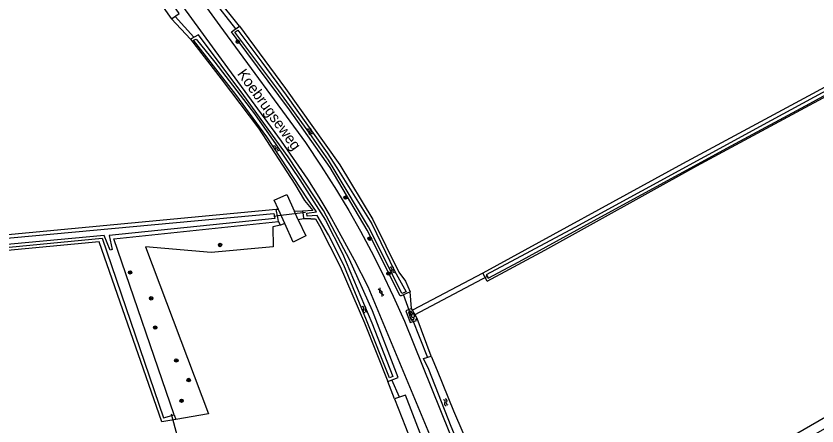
# Model space of a CAD drawing. Extents: x 135999 to 138000, y 396000 to 398501.
# Drawn here: x 136593.9 to 136779.9, y 396708.2 to 396803.6 of the extents above; entities that cross this region are included whole.
import ezdxf

# ---------------------------------------------------------------- set-up
doc = ezdxf.new("R2010")
doc.units = 0
for name, color, linetype in [('gg-anno-openbare ruimte label', 7, 'Continuous'), ('gg-knt-bronhoudergrens', 7, 'Continuous'), ('gg-knt-verharding', 7, 'Continuous'), ('gg-kntw-bovenkant insteek waterloop', 7, 'Continuous'), ('gg-kntw-waterlijn', 7, 'Continuous'), ('gg-kwrk-duiker nz buis', 7, 'Continuous'), ('gt-grn-groengrens', 7, 'Continuous'), ('gt-symb-boom', 7, 'Continuous'), ('gt-symb-gesloten verharding', 7, 'Continuous'), ('gt-symb-watersymbool', 7, 'Continuous'), ('gx-grn-maaiveld', 7, 'Continuous')]:
    doc.layers.add(name, color=color, linetype=linetype)

# ---------------------------------------------------------------- blocks, each defined once
blk = doc.blocks.new('gt0-BOOM')
at = {"layer": 'gt-symb-boom'}
for radius in [0.4, 0.2]:
    blk.add_circle((0, 0), radius, dxfattribs=at)
blk = doc.blocks.new('gt0-GESVH1')
at = {"layer": 'gt-symb-gesloten verharding'}
for p, q in [((-0.99, -0.26), (0.01, 0.24)), ((0.01, -0.26), (-0.99, 0.24)), ((0.01, 0.24), (1.01, -0.26)), ((1.01, 0.24), (0.01, -0.26))]:
    blk.add_line(p, q, dxfattribs=at)
blk = doc.blocks.new('gt0-WA')
at = {"layer": 'gt-symb-watersymbool'}
for centre, start, end in [((-0.32, 0.02), 28.0725, 151.9275), ((0.43, 0.42), 208.0725, 331.9275), ((-0.32, -0.43), 28.0725, 151.9275), ((0.43, -0.03), 208.0725, 331.9275)]:
    blk.add_arc(centre, 0.425, start, end, dxfattribs=at)

msp = doc.modelspace()

# ---------------------------------------------------------------- linework, layer by layer
at = {"layer": 'gg-knt-bronhoudergrens'}
msp.add_line((136690.33, 396724.47), (136687.07, 396733.23), dxfattribs=at)
at = {"layer": 'gg-knt-verharding'}
for points in [[(136588.1, 396874.93), (136623.71, 396825.47), (136641.24, 396801.27), (136661.13, 396774.17), (136664.79, 396768.65), (136668.32, 396763.05), (136671.15, 396758.31), (136673.86, 396753.51), (136676.36, 396748.86), (136678.74, 396744.15), (136681.48, 396738.4), (136684.08, 396732.57), (136704.84, 396681.05)], [(136584.43, 396872.45), (136602.85, 396847.13), (136623.56, 396818.2), (136641.5, 396793.5), (136655.45, 396774.43), (136661.58, 396765.61), (136664.22, 396761.4), (136666.77, 396757.13), (136668.42, 396754.23), (136672.42, 396746.85), (136675.57, 396740.66), (136690.68, 396704.38), (136701.06, 396678.66)]]:
    msp.add_lwpolyline(points, dxfattribs=at)
at = {"layer": 'gg-kntw-bovenkant insteek waterloop'}
for p, q in [((136645.78, 396801.21), (136647.97, 396798.22)), ((136654.68, 396756.7), (136654.31, 396758.54)), ((136660.45, 396758.16), (136660.57, 396757.31)), ((136654.87, 396755.74), (136654.68, 396756.7)), ((136660.57, 396757.31), (136660.69, 396756.44)), ((136662.38, 396756.42), (136663.42, 396756.43)), ((136703.31, 396741.89), (136702.32, 396743.73)), ((136703.12, 396743.36), (136703.54, 396742.62)), ((136685.99, 396735.18), (136685.78, 396735.55)), ((136687.07, 396733.23), (136685.99, 396735.18)), ((136690.33, 396724.47), (136691.7, 396721.1))]:
    msp.add_line(p, q, dxfattribs=at)
for points in [[(136630.03, 396802.89), (136631.77, 396804.16), (136609.31, 396836.49), (136592.68, 396859.89), (136581.76, 396874.66), (136580.74, 396875.78), (136580, 396876.45), (136579.14, 396877.1), (136578.27, 396877.61), (136577.36, 396878.03), (136576.41, 396878.36), (136575.74, 396878.52), (136574.76, 396878.69), (136572.96, 396878.85), (136569.96, 396878.88), (136531.18, 396875.03), (136507.77, 396872.19)], [(136508.57, 396870.21), (136524.15, 396871.93), (136546.01, 396874.18), (136561.49, 396875.6), (136569.04, 396876.21), (136573.12, 396876.33), (136575.86, 396875.99), (136577.65, 396875.22), (136579.07, 396874.22), (136581.26, 396871.43), (136598.94, 396846.62), (136614.6, 396825.01), (136629.68, 396803.27), (136630.03, 396802.89)], [(136872.6, 396836.66), (136849.59, 396824.15), (136810.91, 396802.73), (136748.71, 396769.2), (136702.32, 396743.73)], [(136703.31, 396741.89), (136716.7, 396749.13), (136752, 396768.72), (136805.5, 396797.58), (136858.35, 396826.35), (136874.16, 396834.84)], [(136644.98, 396798.38), (136643.95, 396799.86), (136645.78, 396801.21)], [(136680.21, 396718.56), (136682.65, 396719.51), (136676.65, 396735.03), (136671.34, 396746.9), (136665.27, 396758.33), (136657.11, 396770.82), (136646.81, 396785.04), (136636.23, 396799.15), (136634.37, 396798.15)], [(136634.37, 396798.15), (136641.54, 396788.94), (136650.23, 396777.45), (136658.62, 396764.49), (136660.92, 396760.63)], [(136685.46, 396739.4), (136683.37, 396738.51), (136683.08, 396738.49), (136675.44, 396753.73), (136666.87, 396768.34), (136657.39, 396781.73), (136644.98, 396798.38)], [(136647.97, 396798.22), (136656.44, 396786.73), (136669.07, 396768.94), (136676.76, 396756.23), (136682.77, 396744.02), (136684.35, 396741.87), (136685.46, 396739.4)], [(136654.31, 396758.54), (136466.54, 396740.81), (136458.49, 396761.49), (136452.25, 396777.04), (136449.48, 396784.76), (136449.12, 396785.99)], [(136731.41, 396678.55), (136822, 396730.93), (136912.6, 396783.32), (136912.62, 396784.12), (136911.68, 396785.34), (136820.87, 396732.81), (136730.07, 396680.27), (136730.6, 396679.35), (136731.41, 396678.55)], [(136660.92, 396760.63), (136662.81, 396758.36), (136660.45, 396758.16)], [(136663.42, 396756.43), (136664.4, 396754.79), (136669.19, 396745.32), (136674.86, 396732.21), (136680.21, 396718.56)], [(136630.64, 396710.79), (136616.58, 396751.73), (136654.87, 396755.74)], [(136515.11, 396742.1), (136558.96, 396746.59), (136570.67, 396710.43), (136572.98, 396710.66), (136561.8, 396746.85), (136613.91, 396751.88), (136628.16, 396710.12), (136630.64, 396710.79)], [(136685.78, 396735.55), (136684.45, 396734.99), (136685.43, 396732.28), (136686.91, 396732.76), (136686.78, 396733.09), (136687.07, 396733.23)], [(136689.74, 396721.35), (136688.55, 396723.94), (136690.33, 396724.47)], [(136714.13, 396667.83), (136711.76, 396666.83), (136704.97, 396684.35), (136694.93, 396708.12), (136689.74, 396721.35)], [(136691.7, 396721.1), (136695.51, 396711.74), (136704.86, 396689.99), (136713.15, 396671.67), (136713.71, 396670.24)], [(136712.11, 396639.69), (136707.16, 396654.82), (136699.94, 396675.04), (136684.33, 396715.42), (136681.79, 396714.53)], [(136681.79, 396714.53), (136684.34, 396708.03), (136689.2, 396695.3)]]:
    msp.add_lwpolyline(points, dxfattribs=at)
at = {"layer": 'gg-kntw-waterlijn'}
msp.add_line((136686.19, 396734.19), (136686.48, 396733.67), dxfattribs=at)
for points in [[(136872.63, 396835.6), (136861.18, 396829.32), (136826.21, 396810.15), (136798.37, 396795.07), (136769.27, 396779.22), (136723.68, 396754.37), (136703.12, 396743.36)], [(136703.54, 396742.62), (136710.64, 396746.39), (136730.61, 396757.31), (136747.9, 396766.76), (136759.98, 396773.36), (136778.23, 396783.19), (136786.72, 396787.88), (136805.02, 396797.86), (136834.39, 396813.66), (136847.9, 396821.1), (136863.41, 396829.46), (136873.38, 396834.74), (136872.63, 396835.6)], [(136683.51, 396739.02), (136679.36, 396747.35), (136675.76, 396754.57), (136668, 396767.5), (136666.5, 396770), (136662.12, 396776.21), (136654.9, 396786.12), (136644.73, 396799.8), (136645.38, 396800.28), (136650.94, 396792.81), (136656.66, 396785.11), (136666.17, 396771.77), (136668.37, 396768.27), (136676.55, 396755.25), (136681.81, 396744.34), (136684.52, 396739.39), (136683.51, 396739.02)], [(136661.45, 396757.73), (136663.67, 396758.02), (136661.59, 396761.02), (136652.17, 396775.49), (136644.97, 396785.33), (136635.14, 396797.93), (136635.76, 396798.2), (136640.07, 396792.78), (136649.25, 396780.78), (136654.34, 396773.61), (136659.84, 396765.47), (136665.75, 396756.11), (136669.75, 396748.34), (136676.5, 396732.2), (136681.37, 396719.76), (136680.62, 396719.43)], [(136560.68, 396749.03), (136653.73, 396757.62), (136654.01, 396756.49), (136615.55, 396752.54), (136616.21, 396749.23), (136615.71, 396749.08), (136614.37, 396752.5), (136560.95, 396747.58)], [(136680.62, 396719.43), (136675.28, 396732.85), (136670.02, 396745.64), (136666.5, 396752.66), (136663.86, 396757.18), (136661.5, 396757.01), (136661.45, 396757.73)], [(136686.19, 396734.19), (136685.73, 396734.66), (136685.57, 396734.96), (136685.02, 396734.67), (136685.65, 396732.84), (136686.37, 396733.08), (136686.21, 396733.54), (136686.48, 396733.67)]]:
    msp.add_lwpolyline(points, dxfattribs=at)
at = {"layer": 'gg-kwrk-duiker nz buis'}
for p, q in [((136639.54, 396807.46), (136644.87, 396800.54)), ((136635.22, 396798.61), (136630.82, 396803.47)), ((136703.5, 396743.08), (136686.33, 396733.97)), ((136685.24, 396734.9), (136683.91, 396738.82)), ((136689.53, 396724.07), (136685.95, 396733.08)), ((136682.94, 396714.93), (136681.21, 396718.95)), ((136629.94, 396711.02), (136635.6, 396689.56))]:
    msp.add_line(p, q, dxfattribs=at)
msp.add_lwpolyline([(136661.15, 396757.84), (136654.79, 396757.07), (136653.8, 396756.95)], dxfattribs=at)
at = {"layer": 'gt-grn-groengrens'}
for p, q in [((136645.78, 396801.21), (136640.4, 396807.99)), ((136634.37, 396798.15), (136630.03, 396802.89)), ((136702.32, 396743.73), (136685.99, 396735.18)), ((136685.78, 396735.55), (136685.46, 396739.4)), ((136681.79, 396714.53), (136680.21, 396718.56)), ((136630.64, 396710.79), (136631, 396709.73))]:
    msp.add_line(p, q, dxfattribs=at)
at = {"layer": 'gx-grn-maaiveld'}
for p, q in [((136654.84, 396758.6), (136654.31, 396758.54)), ((136656.3, 396755.34), (136654.84, 396758.6)), ((136660.45, 396758.16), (136658.59, 396758.12)), ((136659.39, 396756.18), (136658.59, 396758.12)), ((136660.69, 396756.4), (136659.39, 396756.18)), ((136660.69, 396756.4), (136660.69, 396756.44)), ((136662.38, 396756.42), (136660.69, 396756.4)), ((136655.3, 396754.95), (136654.87, 396755.74)), ((136656.3, 396755.34), (136655.3, 396754.95))]:
    msp.add_line(p, q, dxfattribs=at)
for points in [[(136654.84, 396758.6), (136653.84, 396760.77), (136656.82, 396762.04), (136658.59, 396758.12)], [(136659.39, 396756.18), (136661.2, 396752.44), (136658.22, 396750.95), (136656.3, 396755.34)], [(136655.3, 396754.95), (136653.54, 396754.53), (136653.59, 396749.86), (136639.23, 396748.54), (136623.98, 396749.89), (136638.59, 396711.06), (136631, 396709.73)], [(136631, 396709.73), (136627.76, 396709.16), (136613.21, 396751.07), (136567.25, 396746.74), (136579.14, 396710.82), (136570.42, 396708.79), (136558.82, 396746.08), (136520.99, 396742.25), (136536.21, 396701.13), (136526.3, 396698.77), (136513.16, 396741.18), (136470.46, 396737.41), (136491.79, 396685.04), (136482.23, 396679.12), (136478.59, 396688.2)]]:
    msp.add_lwpolyline(points, dxfattribs=at)

# ---------------------------------------------------------------- block references
at = {"layer": 'gt-symb-boom'}
for p in [(136645.39, 396797.58), (136670.43, 396761.34), (136641.28, 396750.31), (136676.03, 396751.79), (136620.38, 396743.94), (136680.39, 396743.67), (136625.27, 396737.91), (136626.22, 396731.11), (136631.11, 396723.48), (136633.99, 396718.92), (136632.33, 396714.1)]:
    msp.add_blockref('gt0-BOOM', p, dxfattribs=at)
at = {"layer": 'gt-symb-gesloten verharding', "rotation": 115.33527699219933}
msp.add_blockref('gt0-GESVH1', (136678.64, 396739.34), dxfattribs=at)
at = {"layer": 'gt-symb-watersymbool'}
for p, rotation in [((136662.15, 396776.79), -57.99461679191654), ((136654.33, 396772.88), -57.99461679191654), ((136681.29, 396744.48), 112.02484593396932), ((136674.8, 396735.44), -66.61335784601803), ((136685.61, 396734.11), -67.48588735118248), ((136693.71, 396713.68), 112.02484593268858)]:
    msp.add_blockref('gt0-WA', p, dxfattribs=dict(at, rotation=rotation))

# ---------------------------------------------------------------- texts
at = {"layer": 'gg-anno-openbare ruimte label'}
msp.add_text('Koebrugseweg', height=2.5, rotation=306.1, dxfattribs=at).set_placement((136645.15, 396790.09))

doc.saveas('drawing.dxf')
